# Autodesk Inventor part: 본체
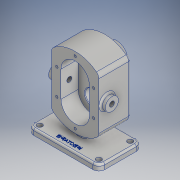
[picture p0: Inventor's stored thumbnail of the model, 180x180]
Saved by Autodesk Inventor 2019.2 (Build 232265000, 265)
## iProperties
Created: 2019-03
Part Number: 본체
Material: 알루미늄 6061
Document SubType Name: Modeling
Designer: User
Density: 2.7 g/cm^3
Appearance: 알루미늄 - 평지
Mass: 1187.13 g
Surface Area: 719.679 cm^2
Volume: 439.678 cm^3
Author: User
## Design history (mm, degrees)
sketch "스케치1"
  geometry: L1 (-36.5, 60)-(36.5, 60); L2 (36.5, 60)-(36.5, -60); L3 (36.5, -60)-(-36.5, -60); L4 (-36.5, -60)-(-36.5, 60); L5 (-51.1, 0)-(51.1, 0) reference; L6 (0, -84)-(0, 84) reference; 1 further point
  constraints: 8 end point, 2 parallel, 1 horizontal, 1 perpendicular
  dimensions: "d0" = 73 distance of L2.end L3.end; "d1" = 120 distance of L1.end L2.end; "d2" = 60 distance between parallel lines of L5 L1; "d3" = 36.5 distance between parallel lines of L6 L2
extrude "돌출1" new body sketch "스케치1" distance "d4" = 10; taper "d5" = 0 deg
fillet "모깎기1" dims "d6" = 10
sketch "스케치2"
  geometry: A1 r 10 centre (26.5, -50) between (26.5, -60) and (36.5, -50) reference; A2 r 10 centre (26.5, 50) between (36.5, 50) and (26.5, 60) reference; A3 r 10 centre (-26.5, 50) between (-26.5, 60) and (-36.5, 50) reference; A4 r 10 centre (-26.5, -50) between (-36.5, -50) and (-26.5, -60) reference; 5 further points
  constraints: 4 coincident
hole "구멍1" sketch "스케치2" at (26.5, -50), (26.5, 50), (-26.5, 50), (-26.5, -50) diameter "d7" = 9; stored, may be unused: countersink angle "d11" = 90 deg, drill point angle "d13" = 118 deg; dims "d8" = 18, "d9" = 4, "d10" = 2, "d12" = 22
fillet "모깎기2" dims "d14" = 3
sketch "스케치6"
  geometry: L1 (-3.096, 78)-(103.096, 78); L2 (-34, 0)-(134, 0) reference; L3 (10, 33.279)-(10, 122.721); L4 (90, 122.721)-(90, 33.279); L5 (90, 8.392)-(10, 147.608); L6 (10, 8.392)-(90, 147.608); L7 (50, -29.522)-(50, 177.129) reference; A1 r 60 centre (50, 78) between (10, 33.279) and (90, 33.279); A2 r 60 centre (50, 78) between (90, 122.721) and (10, 122.721); 1 further point
  constraints: 10 end point, 4 point on circle, 3 midpoint, 2 centre point, 1 horizontal, 1 parallel
  dimensions: "d24" = 78 distance between parallel lines of L2 L1; "d27" = 80 distance of L4.start L3.end; "d68" = 40 distance between parallel lines of L3 L7; "d69" = 40 distance between parallel lines of L4 L7; "d70" = 60 radius of A2; "d71" = 60 radius of A1
extrude "돌출2" join sketch "스케치6" distance "d28" = 53; taper "d29" = 0 deg
sketch "스케치7"
  geometry: L1 (36.5, 0)-(26.5, 0) reference; L2 (36.5, 0)-(-6.5, 0); L3 (-6.5, 0)-(-6.5, 27.707); L4 (-6.5, 27.707)-(36.5, 27.707); L5 (36.5, 27.707)-(36.5, 0); 1 further point
  constraints: 8 end point, 2 parallel, 1 horizontal, 1 perpendicular
  dimensions: "d30" = 43 distance between parallel lines of L5 L3
extrude "돌출3" join sketch "스케치7" stored distance "d31" = 12; taper "d32" = 0 deg
fillet "모깎기3" dims "d33" = 10
sketch "스케치8"
  geometry: L1 (-152.214, 78)-(34.212, 78); L2 (0, 0)-(-100, 0) reference; L3 (-82.648, 100)-(-21.624, 100); L4 (-82.648, 56)-(-21.624, 56); L5 (-74, 100)-(-74, 56); L6 (-26, 100)-(-26, 56); A1 r 24 centre (-50, 100) between (-26, 100) and (-74, 100); A2 r 24 centre (-50, 56) between (-74, 56) and (-26, 56); 1 further point
  constraints: 10 end point, 6 point on line, 4 point on circle, 2 centre point, 2 horizontal, 2 symmetric about line
  dimensions: "d34" = 78 distance between parallel lines of L2 L1; "d35" = 22 distance between parallel lines of L1 L3; "d36" = 48 diameter of A1; "d37" = 48 diameter of A2
extrude "돌출4" cut sketch "스케치8" distance "d38" = 29; taper "d39" = 0 deg
sketch "스케치9"
  geometry: L1 (-140.527, 78)-(33.666, 78); L2 (0, 0)-(-100, 0) reference; C1 r 12.5 at (-50, 100); C2 r 12.5 at (-50, 56); 1 further point
  constraints: 2 centre point, 2 end point, 1 horizontal
  dimensions: "d40" = 25 diameter of C1; "d41" = 78 distance between parallel lines of L2 L1; "d42" = 25 diameter of C2; "d43" = 22 distance from line of L1 C2.centre; "d44" = 22 distance from line of L1 C1.centre
extrude "돌출5" cut sketch "스케치9" distance "d45" = 15; taper "d46" = 0 deg
sketch "스케치11"
  geometry: L1 (-34, 0)-(134, 0) reference; C1 r 19 at (50, 100); 1 further point
  constraints: 1 centre point
  dimensions: "d48" = 100 distance from line of L1 C1.centre; "d49" = 38 diameter of C1
extrude "돌출6" join sketch "스케치11" distance "d50" = 17; taper "d51" = 0 deg
sketch "스케치12"
  geometry: C1 r 19 at (0, 0) reference; 2 further points
  constraints: 1 coincident
hole "구멍2" sketch "스케치12" at (0, 0) diameter "d52" = 17; stored, may be unused: countersink angle "d56" = 90 deg, drill point angle "d58" = 118 deg; dims "d53" = 18, "d54" = 28, "d55" = 7.3, "d57" = 22
sketch "스케치14"
  geometry: L1 (-87.6, -38)-(14.6, -38) reference; L2 (-53, 0)-(-53, 80) reference; C1 r 11 at (-39, 40); 1 further point
  constraints: 1 centre point
  dimensions: "d63" = 22 diameter of C1; "d64" = 78 distance from line of C1.centre L1; "d65" = 14 distance from line of C1.centre L2
extrude "돌출7" join sketch "스케치14" distance "d66" = 8; taper "d67" = 0 deg
sketch "스케치13"
  geometry: L1 (0, 0)-(-100, 0) reference; L2 (-110.295, 78)-(9.201, 78); C1 r 12.5 at (-50, 56) reference; A1 r 31 centre (-50, 56) between (-81, 56) and (-19, 56); A2 r 31 centre (-50, 100) between (-81, 100) and (-19, 100); 3 further points
  constraints: 4 point on circle, 2 centre point, 2 end point, 1 concentric, 1 horizontal, 1 symmetric about line, 1 other
  dimensions: "d72" = 106 distance of point (-50, 25) point (-50, 131); "d73" = 78 distance between parallel lines of L1 L2; "d74" = 53 distance from line of L2 point (-50, 131); "d75" = 62 diameter of A1
hole "구멍3" sketch "스케치13" at (-81, 100), (-50, 131), (-19, 100), (-19, 56), (-81, 56), (-50, 25) diameter "d76" = 4.134; stored, may be unused: countersink angle "d80" = 90 deg, drill point angle "d82" = 118 deg; dims "d77" = 10, "d78" = 4, "d79" = 2, "d81" = 12
sketch "스케치15"
  geometry: C1 r 11 at (0, 0) reference; 2 further points
  constraints: 1 coincident
hole "구멍4" sketch "스케치15" at (0, 0) diameter "d83" = 8.376; stored, may be unused: countersink angle "d87" = 90 deg, drill point angle "d89" = 118 deg; dims "d84" = 100, "d85" = 4, "d86" = 2, "d88" = 12
sketch "스케치16"
  geometry: L1 (26.5, 60)-(-26.5, 60) reference; L2 (-36.5, 50)-(-36.5, -50) reference; 2 further points
  constraints: 1 other
  dimensions: "d90" = 60 distance from line of point (-26.5, 0) L1; "d91" = 10 distance from line of L2 point (-26.5, 0)
feature "엠보싱1" sketch "스케치16" dims "d0" = 73, "d1" = 120, "d2" = 60, "d3" = 36.5, "d92" = 0.5, "d93" = 0
fillet "모깎기4" dims "d94" = 3
chamfer "모따기1" distance "d95" = 1; stored, may be unused: second distance "d96" = 2, angle "d97" = 45 deg
fillet "모깎기5" dims "d101" = 0.5
fillet "모깎기6" dims "d102" = 3
fillet "모깎기7" dims "d103" = 3
fillet "모깎기8" dims "d104" = 3
fillet "모깎기9" dims "d105" = 3
fillet "모깎기10" dims "d106" = 3
sketch "스케치17"
  geometry: L1 (-31.7, 100)-(115.473, 100); L2 (36.5, 0)-(26.5, 0) reference; L3 (53.5, 114.404)-(52.8, 114); L4 (52.8, 114)-(52.8, 100); L5 (53.5, 114)-(53.5, 86) reference; L6 (53.5, 114.404)-(53.5, 100); L7 (52.8, 100)-(53.5, 100); L8 (46.7, 114)-(53.5, 114) reference; 1 further point
  constraints: 10 end point, 3 point on line, 1 horizontal, 1 midpoint, 1 perpendicular
  dimensions: "d114" = 100 distance between parallel lines of L2 L1; "d115" = 0.7 distance from line of L5 L4.end; "d116" = 30 deg angle of L1 L3
revolve "회전1" sketch "스케치17" stored, may be unused: angle "d117" = 90 deg
node "솔리드1"
mirror "미러1"
